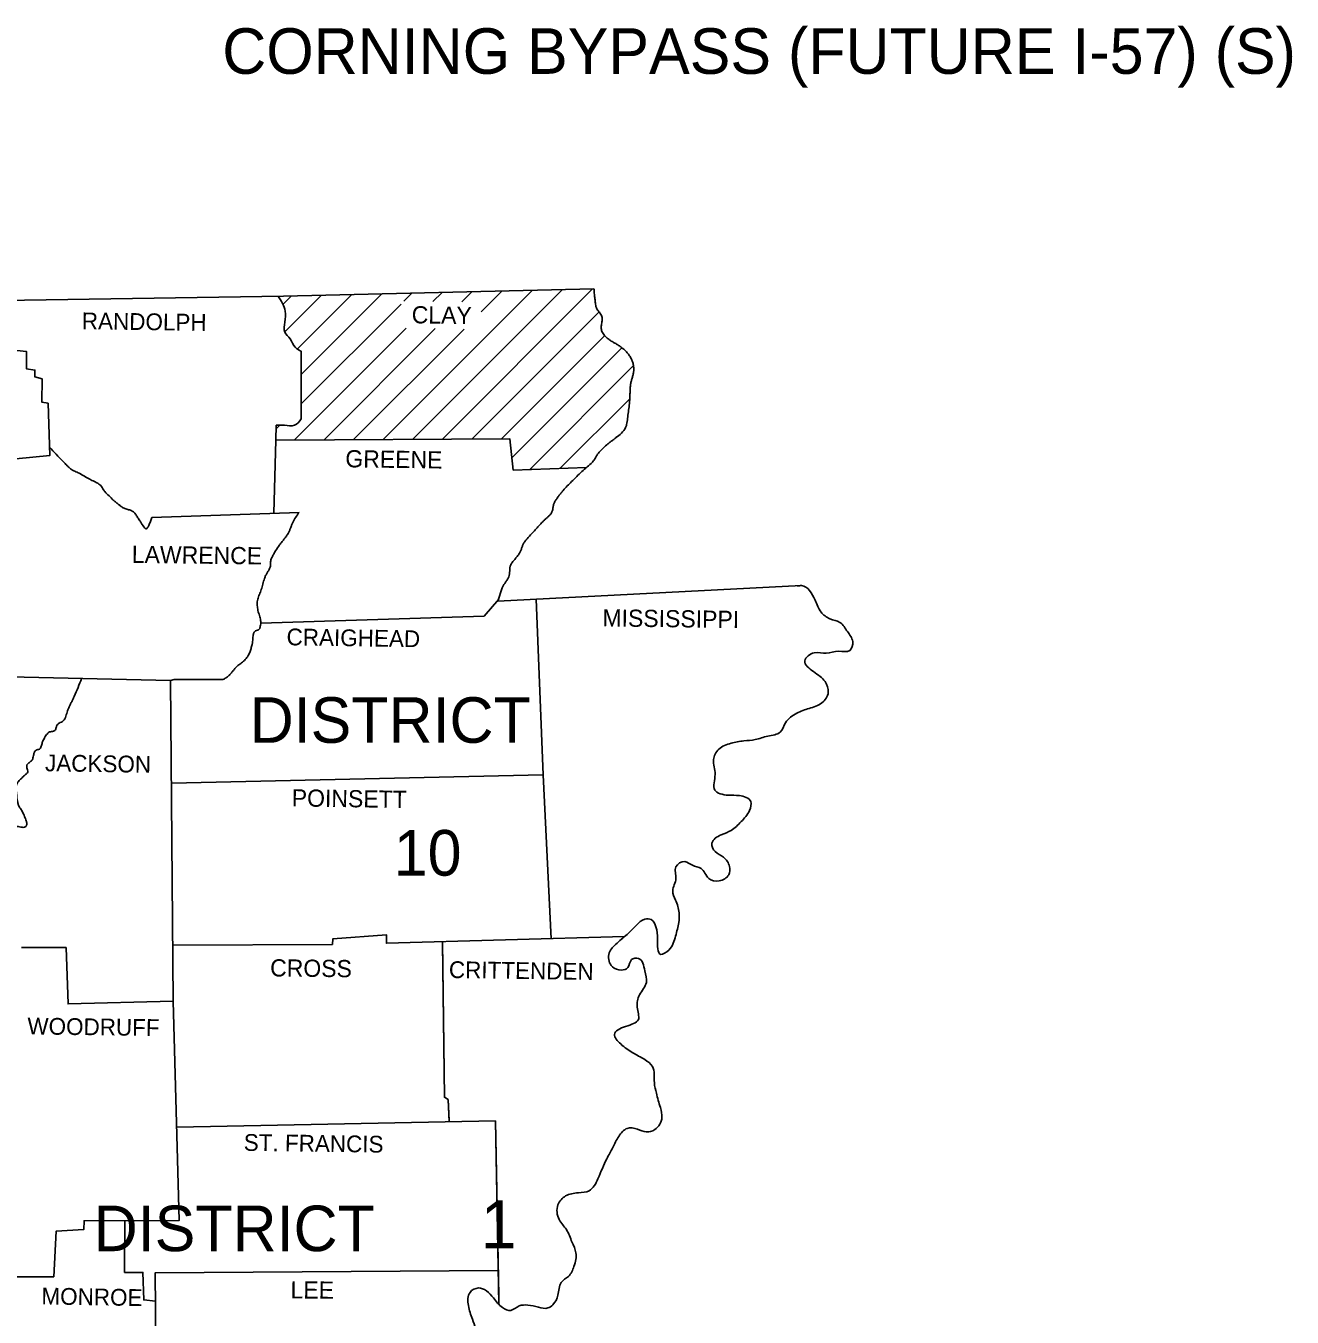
# Model space of a CAD drawing. Extents: x 1164457 to 1439835, y 1590918 to 1773502.
# Drawn here: x 1408167 to 1439835, y 1736445 to 1768732 of the extents above; entities that cross this region are included whole.
import ezdxf

# ---------------------------------------------------------------- set-up
doc = ezdxf.new("R2010")
doc.units = 0
for name, color, linetype in [('1', 7, 'Continuous'), ('Default', 7, 'Continuous'), ('G-ANNO-TEXT', 7, 'Continuous'), ('R_Draft', 7, 'Continuous')]:
    doc.layers.add(name, color=color, linetype=linetype)

msp = doc.modelspace()

# ---------------------------------------------------------------- linework, layer by layer
at = {"layer": '1'}
for p, q in [((1419975, 1754345), (1420083, 1754677)), ((1408055, 1745685), (1409173, 1745685))]:
    msp.add_line(p, q, dxfattribs=at)
for points in [[(1367515, 1761696), (1383685, 1761686), (1397875, 1761716), (1414615, 1761976), (1422375, 1762156)], [(1407073, 1761858), (1407035, 1761556), (1407235, 1761526), (1407225, 1761405), (1407455, 1761355), (1407475, 1761195), (1407585, 1761125), (1407615, 1760645), (1408185, 1760585), (1408185, 1760155), (1408395, 1760125), (1408395, 1759955), (1408575, 1759905), (1408565, 1759325), (1408725, 1759295), (1408765, 1757985), (1407915, 1757905), (1407925, 1757625), (1407665, 1757615), (1407755, 1752455), (1411785, 1752365), (1411855, 1744345), (1409225, 1744275), (1409173, 1745685)], [(1419975, 1754345), (1427565, 1754735)], [(1411843, 1745744), (1415835, 1745765), (1415845, 1745905), (1417185, 1746005), (1417185, 1745795), (1423142, 1745959)]]:
    msp.add_lwpolyline(points, dxfattribs=at)
for points in [[(1422375, 1762156), (1422384, 1762045), (1422395, 1761935), (1422409, 1761825), (1422425, 1761716), (1422448, 1761654), (1422489, 1761598), (1422532, 1761543), (1422565, 1761486), (1422578, 1761384), (1422565, 1761275), (1422558, 1761166), (1422565, 1761114), (1422585, 1761065), (1422661, 1760967), (1422755, 1760885), (1422827, 1760838), (1422900, 1760796), (1422974, 1760754), (1423045, 1760705), (1423189, 1760577), (1423251, 1760503), (1423279, 1760461), (1423305, 1760415), (1423341, 1760331), (1423362, 1760246), (1423370, 1760160), (1423365, 1760075), (1423348, 1759988), (1423323, 1759901), (1423299, 1759814), (1423285, 1759725), (1423280, 1759628), (1423276, 1759531), (1423272, 1759433), (1423265, 1759335), (1423225, 1758995), (1423206, 1758839), (1423191, 1758762), (1423179, 1758723), (1423165, 1758685), (1423061, 1758547), (1422925, 1758435), (1422868, 1758390), (1422809, 1758346), (1422751, 1758302), (1422695, 1758255), (1422485, 1758045), (1422446, 1757992), (1422412, 1757933), (1422377, 1757876), (1422335, 1757825), (1422075, 1757585), (1421815, 1757335), (1421605, 1757115), (1421548, 1757049), (1421494, 1756980), (1421444, 1756908), (1421395, 1756835), (1421364, 1756760), (1421350, 1756677), (1421332, 1756596), (1421317, 1756559), (1421295, 1756525), (1421240, 1756468), (1421181, 1756415), (1421121, 1756362), (1421065, 1756305), (1420885, 1756105), (1420645, 1755835), (1420606, 1755774), (1420578, 1755704), (1420555, 1755633), (1420525, 1755565), (1420471, 1755486), (1420409, 1755411), (1420347, 1755336), (1420295, 1755255), (1420274, 1755184), (1420268, 1755106), (1420263, 1755028), (1420245, 1754955), (1420212, 1754893), (1420173, 1754834), (1420132, 1754775), (1420095, 1754715), (1420083, 1754677)], [(1427455, 1754725), (1427565, 1754735), (1427905, 1754375), (1428055, 1754075), (1428275, 1753905), (1428525, 1753815), (1428715, 1753585), (1428845, 1753335), (1428775, 1753115), (1428495, 1753095), (1428185, 1753045), (1427885, 1753055), (1427645, 1752855), (1427865, 1752585), (1428155, 1752335), (1428235, 1752065), (1428075, 1751805), (1427755, 1751665), (1427445, 1751545), (1427165, 1751305), (1427035, 1751075), (1426725, 1750975), (1426405, 1750885), (1426125, 1750855), (1425805, 1750795), (1425495, 1750645), (1425365, 1750385), (1425405, 1750015), (1425395, 1749625), (1425725, 1749495), (1426015, 1749485), (1426295, 1749335), (1426265, 1749115), (1426055, 1748835), (1425805, 1748615), (1425555, 1748505), (1425325, 1748295), (1425405, 1748085), (1425615, 1747945), (1425765, 1747715), (1425745, 1747505), (1425505, 1747355), (1425245, 1747415), (1425055, 1747665), (1424835, 1747745), (1424645, 1747835), (1424425, 1747705), (1424425, 1747415), (1424345, 1747105), (1424415, 1746875), (1424505, 1746555), (1424495, 1746315), (1424415, 1745975), (1424245, 1745625), (1424045, 1745515), (1423965, 1745895), (1423925, 1746205), (1423805, 1746385), (1423645, 1746395), (1423435, 1746245), (1423205, 1746015), (1422915, 1745765), (1422745, 1745515), (1422835, 1745205), (1423055, 1745125), (1423225, 1745185), (1423315, 1745385), (1423485, 1745415), (1423645, 1745105)], [(1423645, 1745105), (1423685, 1744815), (1423515, 1744505), (1423455, 1744195), (1423485, 1743885), (1423165, 1743715), (1422885, 1743515), (1423045, 1743275), (1423345, 1743055), (1423645, 1742885), (1423835, 1742715), (1423885, 1742305), (1423935, 1742045), (1424035, 1741685), (1424075, 1741435), (1423895, 1741135), (1423685, 1741075), (1423465, 1741145), (1423205, 1741165), (1422995, 1740965), (1422845, 1740685), (1422695, 1740405), (1422585, 1740165), (1422475, 1739905), (1422255, 1739605), (1421985, 1739555), (1421665, 1739475), (1421475, 1739255), (1421505, 1738885), (1421685, 1738635), (1421825, 1738325), (1421925, 1738055), (1421875, 1737715), (1421735, 1737465), (1421555, 1737315), (1421475, 1736995), (1421345, 1736755), (1421225, 1736675), (1420985, 1736695), (1420725, 1736745), (1420505, 1736725), (1420295, 1736615), (1420085, 1736685), (1419865, 1736925), (1419685, 1737105), (1419485, 1737175), (1419275, 1737065), (1419235, 1736735), (1419335, 1736395), (1419425, 1735935), (1419335, 1735655), (1419305, 1735195)]]:
    msp.add_spline(points, degree=3, dxfattribs=at)
at = {"layer": 'Default'}
msp.add_line((1414416, 1758376), (1414425, 1758745), dxfattribs=at)
for points in [[(1415055, 1760595), (1415055, 1758905)], [(1414372, 1756543), (1414416, 1758376), (1414425, 1758375), (1420275, 1758405), (1420355, 1757625), (1422191, 1757692)], [(1411315, 1756435), (1415002, 1756565)], [(1414041, 1753794), (1419625, 1753975), (1419992, 1754398)], [(1420933, 1754395), (1421105, 1750005), (1421308, 1745908)], [(1413095, 1752385), (1411875, 1752385), (1411785, 1752365)], [(1421105, 1750005), (1411808, 1749793)], [(1418585, 1745834), (1418635, 1741945), (1418725, 1741885), (1418757, 1741332)], [(1418585, 1745795), (1418635, 1741945), (1418725, 1741885), (1418755, 1741365)], [(1418585, 1745795), (1418635, 1741945), (1418725, 1741885), (1418755, 1741365)], [(1418585, 1745795), (1418635, 1741945), (1418725, 1741885), (1418755, 1741365)], [(1418585, 1745795), (1418635, 1741945), (1418725, 1741885), (1418755, 1741365)], [(1411855, 1744345), (1412005, 1738865), (1409625, 1738855), (1409615, 1738635), (1408925, 1738595), (1408865, 1737455), (1407917, 1737455)], [(1411941, 1741194), (1419915, 1741355)], [(1419915, 1741355), (1419995, 1736975)], [(1419915, 1741355), (1419995, 1736975)], [(1419915, 1741355), (1419995, 1736975)], [(1419915, 1741355), (1419995, 1736975)], [(1419915, 1741355), (1419995, 1736975)], [(1419915, 1741355), (1419995, 1736975)], [(1419915, 1741355), (1419995, 1736975)], [(1419915, 1741355), (1419999, 1736774)], [(1410645, 1738859), (1410635, 1737565), (1411095, 1737565), (1411115, 1736875), (1411410, 1736844)], [(1411822, 1728685), (1412755, 1728745), (1412745, 1730775), (1412015, 1730825), (1412055, 1734795), (1411425, 1734885), (1411405, 1737555), (1419983, 1737615)]]:
    msp.add_lwpolyline(points, dxfattribs=at)
for points in [[(1414474, 1761973), (1414655, 1761596), (1414645, 1761325), (1414645, 1761075), (1414775, 1760905), (1414905, 1760695), (1415055, 1760595)], [(1415055, 1758905), (1414885, 1758745), (1414635, 1758745), (1414425, 1758745)], [(1408759, 1758196), (1408926, 1758020), (1409095, 1757845), (1409119, 1757821), (1409188, 1757748), (1409235, 1757701), (1409260, 1757678), (1409272, 1757666), (1409285, 1757655), (1409336, 1757621), (1409392, 1757596), (1409450, 1757572), (1409505, 1757545), (1409635, 1757470), (1409765, 1757395), (1409822, 1757366), (1409881, 1757338), (1409967, 1757293), (1409981, 1757284), (1409995, 1757275), (1410039, 1757235), (1410075, 1757185), (1410108, 1757133), (1410125, 1757108), (1410145, 1757085), (1410248, 1756979), (1410355, 1756875), (1410406, 1756830), (1410458, 1756787), (1410511, 1756746), (1410565, 1756705), (1410647, 1756663), (1410738, 1756634), (1410825, 1756601), (1410863, 1756577), (1410880, 1756562), (1410895, 1756545), (1410925, 1756504), (1410951, 1756461), (1410977, 1756418), (1411005, 1756375), (1411024, 1756348), (1411042, 1756319), (1411080, 1756260), (1411118, 1756207), (1411136, 1756184), (1411146, 1756174), (1411150, 1756170), (1411155, 1756165), (1411166, 1756158), (1411178, 1756157), (1411200, 1756170), (1411243, 1756242), (1411283, 1756342), (1411300, 1756392), (1411315, 1756435)], [(1415002, 1756565), (1414917, 1756443), (1414845, 1756315), (1414814, 1756246), (1414787, 1756174), (1414759, 1756103), (1414725, 1756035), (1414669, 1755953), (1414607, 1755874), (1414545, 1755796), (1414485, 1755715), (1414388, 1755564), (1414345, 1755486), (1414305, 1755405), (1414291, 1755354), (1414288, 1755301), (1414286, 1755247), (1414275, 1755195), (1414242, 1755125), (1414204, 1755056), (1414165, 1754987), (1414135, 1754915), (1414114, 1754846), (1414095, 1754775), (1414076, 1754705), (1414055, 1754635), (1414033, 1754575), (1414009, 1754516), (1413985, 1754456), (1413965, 1754395), (1413954, 1754334), (1413952, 1754271), (1413957, 1754207), (1413965, 1754145), (1413979, 1754082), (1413999, 1754020), (1414019, 1753958), (1414035, 1753895), (1414041, 1753838), (1414040, 1753780), (1414031, 1753722), (1414024, 1753693), (1414015, 1753665), (1413985, 1753631), (1413938, 1753610), (1413892, 1753589), (1413865, 1753555), (1413857, 1753520), (1413852, 1753484), (1413845, 1753410), (1413838, 1753337), (1413825, 1753265), (1413799, 1753165), (1413765, 1753065), (1413710, 1752959), (1413675, 1752911), (1413635, 1752865), (1413589, 1752825), (1413540, 1752789), (1413491, 1752754), (1413445, 1752715), (1413394, 1752660), (1413346, 1752601), (1413298, 1752541), (1413245, 1752485), (1413175, 1752430), (1413136, 1752407), (1413095, 1752385)], [(1409562, 1752415), (1409472, 1752189), (1409375, 1751965), (1409340, 1751890), (1409305, 1751815), (1409270, 1751740), (1409235, 1751665), (1409210, 1751601), (1409190, 1751535), (1409170, 1751469), (1409145, 1751405), (1409108, 1751359), (1409056, 1751325), (1409001, 1751293), (1408976, 1751276), (1408955, 1751255), (1408937, 1751223), (1408926, 1751185), (1408914, 1751147), (1408895, 1751115), (1408857, 1751095), (1408810, 1751087), (1408763, 1751078), (1408725, 1751055), (1408706, 1751032), (1408688, 1751009), (1408654, 1750959), (1408623, 1750908), (1408595, 1750855), (1408578, 1750811), (1408566, 1750764), (1408553, 1750718), (1408535, 1750675), (1408507, 1750649), (1408467, 1750634), (1408426, 1750619), (1408395, 1750595), (1408381, 1750571), (1408371, 1750544), (1408358, 1750486), (1408346, 1750427), (1408332, 1750387), (1408325, 1750375), (1408296, 1750344), (1408259, 1750316), (1408223, 1750288), (1408195, 1750255), (1408190, 1750208), (1408204, 1750154), (1408217, 1750100), (1408205, 1750055), (1408197, 1750046), (1408188, 1750036), (1408131, 1749985), (1408091, 1749951), (1408055, 1749915), (1408021, 1749878), (1407987, 1749841), (1407957, 1749801), (1407945, 1749779), (1407935, 1749755), (1407923, 1749646), (1407935, 1749535), (1407942, 1749462), (1407951, 1749389), (1407964, 1749317), (1407973, 1749281), (1407985, 1749245), (1408007, 1749200), (1408033, 1749159), (1408060, 1749118), (1408085, 1749075), (1408134, 1748966), (1408155, 1748911), (1408175, 1748855), (1408186, 1748820), (1408193, 1748782), (1408188, 1748745), (1408179, 1748729), (1408173, 1748722), (1408165, 1748715), (1408104, 1748692), (1408041, 1748698), (1407977, 1748713), (1407946, 1748717), (1407915, 1748715), (1407862, 1748706), (1407810, 1748698), (1407757, 1748687), (1407705, 1748675)]]:
    msp.add_spline(points, degree=3, dxfattribs=at)
at = {"layer": 'R_Draft'}
for p, q in [((1414606, 1761774), (1414812, 1761980)), ((1414645, 1761077), (1415565, 1761998)), ((1414958, 1760655), (1416318, 1762015)), ((1415055, 1760017), (1417071, 1762032)), ((1417105, 1758389), (1420835, 1762120)), ((1417623, 1761849), (1417824, 1762050)), ((1417844, 1758393), (1421588, 1762137)), ((1418349, 1761839), (1418577, 1762067)), ((1418583, 1758397), (1422341, 1762155)), ((1419074, 1761829), (1419330, 1762085)), ((1419558, 1761578), (1420082, 1762102)), ((1415055, 1759281), (1417550, 1761776)), ((1419322, 1758401), (1422502, 1761581)), ((1414887, 1758378), (1417679, 1761169)), ((1415626, 1758382), (1418404, 1761160)), ((1416365, 1758385), (1419130, 1761150)), ((1420061, 1758404), (1422643, 1760986)), ((1420324, 1757931), (1423075, 1760682)), ((1420768, 1757640), (1423364, 1760236)), ((1421531, 1757668), (1423271, 1759408)), ((1414423, 1758649), (1414519, 1758745))]:
    msp.add_line(p, q, dxfattribs=at)

# ---------------------------------------------------------------- texts
at = {"layer": 'Default'}
for s, height, rotation, p in [('RANDOLPH', 420.1, 359.2583, (1409565, 1761145)), ('CLAY', 430, 359.2258, (1417815, 1761295)), ('GREENE', 430.1, 359.2361, (1416155, 1757695)), ('LAWRENCE', 430.1, 359.2678, (1410815, 1755305)), ('MISSISSIPPI', 429.96, 359.3097, (1422585, 1753715)), ('CRAIGHEAD', 420.1, 359.1159, (1414685, 1753245)), ('JACKSON', 419.9, 359.1352, (1408645, 1750095)), ('POINSETT', 430, 359.1987, (1414815, 1749215)), ('CROSS', 430, 359.3839, (1414275, 1744965)), ('CRITTENDEN', 420.1, 359.213, (1418745, 1744925)), ('WOODRUFF', 419.9, 359.2748, (1408205, 1743515)), ('ST. FRANCIS', 419.94, 359.2216, (1413615, 1740605)), ('MONROE', 419.9, 359.0331, (1408555, 1736765)), ('LEE', 430.1, 359.4327, (1414785, 1736915))]:
    msp.add_text(s, height=height, rotation=rotation, dxfattribs=at).set_placement(p)
for s, height, p in [('DISTRICT', 1140, (1413765, 1750805)), ('10', 1140, (1417368, 1747485)), ('1', 1200, (1419545, 1738165)), ('DISTRICT', 1140, (1409865, 1738095))]:
    msp.add_text(s, height=height, dxfattribs=at).set_placement(p)
at = {"layer": 'G-ANNO-TEXT'}
msp.add_text('CORNING BYPASS (FUTURE I-57) (S)', height=1140, dxfattribs=at).set_placement((1413080, 1767531))

doc.saveas('drawing.dxf')
